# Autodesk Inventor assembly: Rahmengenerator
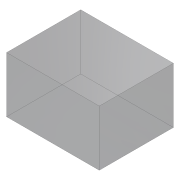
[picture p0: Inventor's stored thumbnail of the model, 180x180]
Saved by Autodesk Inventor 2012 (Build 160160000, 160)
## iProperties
Created: 2011-09
Part Number: Rahmengenerator
Document SubType Name: Assembly
Designer: Administrator
_SolveAssemblyDoc: Frame Generator Solve Assembly
_Version: 15.0.0
Author: Administrator
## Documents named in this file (2)
- C:\DemoDaten2012\CAD Daten\Gestell-Generator\Gestell-Generator.iam
- C:\DemoDaten2012\CAD Daten\Gestell-Generator\Box.ipt
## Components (1 placed, 1 different names)
1. Box:1
